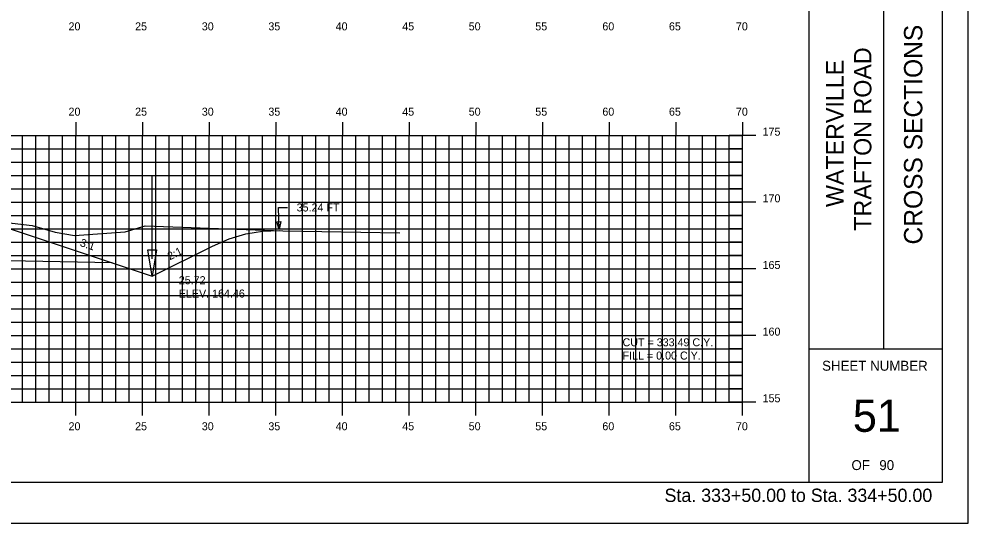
# Model space of a CAD drawing. Extents: x 1141868 to 1142038, y 608981 to 609091.
# Drawn here: x 1141966.5 to 1142037.7, y 608981.3 to 609019.1 of the extents above; entities that cross this region are included whole.
import ezdxf

# ---------------------------------------------------------------- set-up
doc = ezdxf.new("R2010")
doc.units = 0
for name, color, linetype in [('ANNOTATION', 7, 'Continuous'), ('BORDER', 7, 'Continuous'), ('D_Drainage_Ditch_Line', 7, 'Continuous'), ('D_Roadway_SlopeLines', 7, 'Continuous'), ('D_Roadway_SubGrade', 7, 'Continuous'), ('D_Text_Standard', 7, 'Continuous'), ('H_V ANNOTATION', 7, 'Continuous'), ('HIGHWAY_TITLE', 7, 'Continuous'), ('MAJOR', 7, 'Continuous'), ('MINOR', 7, 'Continuous'), ('PLOT BOUNDARY', 7, 'Continuous'), ('S_Roadway_Centerline', 7, 'Continuous')]:
    doc.layers.add(name, color=color, linetype=linetype)

msp = doc.modelspace()

# ---------------------------------------------------------------- linework, layer by layer
msp.add_lwpolyline([(1141914.544, 609003.78), (1141914.544, 609003.78), (1141915.794, 609003.711), (1141917.044, 609003.482), (1141918.294, 609003.095), (1141919.544, 609002.55), (1141925.059, 608999.792), (1141928.059, 609000.792), (1141935.783, 609003.367), (1141935.784, 609003.367), (1141939.784, 609003.527), (1141950.784, 609003.747), (1141961.784, 609003.527), (1141965.784, 609003.367), (1141973.507, 609000.792), (1141976.507, 608999.792), (1141981.022, 609002.05), (1141982.272, 609002.591), (1141983.522, 609002.965), (1141984.772, 609003.172), (1141986.022, 609003.211)])
at = {"layer": 'BORDER'}
for p, q in [((1142025.784, 608984.335), (1142025.784, 609089.335)), ((1142031.375, 608994.338), (1142031.375, 609029.338)), ((1142025.784, 608994.338), (1142035.784, 608994.338))]:
    msp.add_line(p, q, dxfattribs=at)
msp.add_lwpolyline([(1141875.784, 608984.335), (1142035.784, 608984.335), (1142035.784, 609089.335), (1141875.784, 609089.335)], close=True, dxfattribs=at)
at = {"layer": 'D_Drainage_Ditch_Line'}
msp.add_line((1141976.507, 609001.104), (1141976.508, 609007.348), dxfattribs=at)
msp.add_lwpolyline([(1141976.179, 609001.761), (1141976.835, 609001.761), (1141976.507, 608999.792)], close=True, dxfattribs=at)
at = {"layer": 'D_Roadway_SlopeLines'}
for points in [[(1141976.507, 608999.792), (1141981.022, 609002.05), (1141982.272, 609002.591), (1141983.522, 609002.965), (1141984.772, 609003.172), (1141986.022, 609003.211)], [(1141973.507, 609000.792), (1141976.507, 608999.792)]]:
    msp.add_lwpolyline(points, dxfattribs=at)
at = {"layer": 'D_Roadway_SubGrade'}
msp.add_lwpolyline([(1141961.784, 609003.11), (1141961.784, 609003.277), (1141965.784, 609003.117), (1141965.784, 609003.367), (1141965.784, 609003.367), (1141973.507, 609000.792), (1141961.784, 609001.027)], close=True, dxfattribs=at)
at = {"layer": 'D_Text_Standard'}
msp.add_lwpolyline([(1141986.022, 609003.3), (1141985.986, 609004.95), (1141986.666, 609004.95)], dxfattribs=at)
msp.add_lwpolyline([(1141986.022, 609003.3), (1141985.864, 609003.878), (1141986.155, 609003.885)], close=True, dxfattribs=at)
at = {"layer": 'MAJOR'}
for p, q in [((1141970.784, 609011.337), (1141970.784, 609010.335)), ((1141975.784, 609011.337), (1141975.784, 609010.335)), ((1141980.784, 609011.337), (1141980.784, 609010.335)), ((1141985.784, 609011.337), (1141985.784, 609010.335)), ((1141990.784, 609011.337), (1141990.784, 609010.335)), ((1141995.784, 609011.337), (1141995.784, 609010.335)), ((1142000.784, 609011.337), (1142000.784, 609010.335)), ((1142005.784, 609011.337), (1142005.784, 609010.335)), ((1142010.784, 609011.337), (1142010.784, 609010.335)), ((1142015.784, 609011.337), (1142015.784, 609010.335)), ((1142020.784, 609011.337), (1142020.784, 609010.335)), ((1141880.784, 609010.335), (1142020.784, 609010.335)), ((1141880.784, 609010.335), (1142020.784, 609010.335)), ((1141970.784, 608990.335), (1141970.784, 609010.335)), ((1141975.784, 608990.335), (1141975.784, 609010.335)), ((1141980.784, 608990.335), (1141980.784, 609010.335)), ((1141985.784, 608990.335), (1141985.784, 609010.335)), ((1141990.784, 608990.335), (1141990.784, 609010.335)), ((1141995.784, 608990.335), (1141995.784, 609010.335)), ((1142000.784, 608990.335), (1142000.784, 609010.335)), ((1142005.784, 608990.335), (1142005.784, 609010.335)), ((1142010.784, 608990.335), (1142010.784, 609010.335)), ((1142015.784, 608990.335), (1142015.784, 609010.335)), ((1142021.786, 609010.335), (1142019.782, 609010.335)), ((1142020.784, 608990.335), (1142020.784, 609010.335)), ((1142020.784, 608990.335), (1142020.784, 609010.335)), ((1141880.784, 609005.335), (1142020.784, 609005.335)), ((1142021.786, 609005.335), (1142019.782, 609005.335)), ((1141880.784, 609000.335), (1142020.784, 609000.335)), ((1142021.786, 609000.335), (1142019.782, 609000.335)), ((1141880.784, 608995.335), (1142020.784, 608995.335)), ((1142021.786, 608995.335), (1142019.782, 608995.335)), ((1141880.784, 608990.335), (1142020.784, 608990.335)), ((1141880.784, 608990.335), (1142020.784, 608990.335)), ((1141970.784, 608989.333), (1141970.784, 608990.335)), ((1141975.784, 608989.333), (1141975.784, 608990.335)), ((1141980.784, 608989.333), (1141980.784, 608990.335)), ((1141985.784, 608989.333), (1141985.784, 608990.335)), ((1141990.784, 608989.333), (1141990.784, 608990.335)), ((1141995.784, 608989.333), (1141995.784, 608990.335)), ((1142000.784, 608989.333), (1142000.784, 608990.335)), ((1142005.784, 608989.333), (1142005.784, 608990.335)), ((1142010.784, 608989.333), (1142010.784, 608990.335)), ((1142015.784, 608989.333), (1142015.784, 608990.335)), ((1142021.786, 608990.335), (1142019.782, 608990.335)), ((1142020.784, 608989.333), (1142020.784, 608990.335))]:
    msp.add_line(p, q, dxfattribs=at)
at = {"layer": 'MINOR'}
for p, q in [((1141966.784, 608990.335), (1141966.784, 609010.335)), ((1141967.784, 608990.335), (1141967.784, 609010.335)), ((1141968.784, 608990.335), (1141968.784, 609010.335)), ((1141969.784, 608990.335), (1141969.784, 609010.335)), ((1141971.784, 608990.335), (1141971.784, 609010.335)), ((1141972.784, 608990.335), (1141972.784, 609010.335)), ((1141973.784, 608990.335), (1141973.784, 609010.335)), ((1141974.784, 608990.335), (1141974.784, 609010.335)), ((1141976.784, 608990.335), (1141976.784, 609010.335)), ((1141977.784, 608990.335), (1141977.784, 609010.335)), ((1141978.784, 608990.335), (1141978.784, 609010.335)), ((1141979.784, 608990.335), (1141979.784, 609010.335)), ((1141981.784, 608990.335), (1141981.784, 609010.335)), ((1141982.784, 608990.335), (1141982.784, 609010.335)), ((1141983.784, 608990.335), (1141983.784, 609010.335)), ((1141984.784, 608990.335), (1141984.784, 609010.335)), ((1141986.784, 608990.335), (1141986.784, 609010.335)), ((1141987.784, 608990.335), (1141987.784, 609010.335)), ((1141988.784, 608990.335), (1141988.784, 609010.335)), ((1141989.784, 608990.335), (1141989.784, 609010.335)), ((1141991.784, 608990.335), (1141991.784, 609010.335)), ((1141992.784, 608990.335), (1141992.784, 609010.335)), ((1141993.784, 608990.335), (1141993.784, 609010.335)), ((1141994.784, 608990.335), (1141994.784, 609010.335)), ((1141996.784, 608990.335), (1141996.784, 609010.335)), ((1141997.784, 608990.335), (1141997.784, 609010.335)), ((1141998.784, 608990.335), (1141998.784, 609010.335)), ((1141999.784, 608990.335), (1141999.784, 609010.335)), ((1142001.784, 608990.335), (1142001.784, 609010.335)), ((1142002.784, 608990.335), (1142002.784, 609010.335)), ((1142003.784, 608990.335), (1142003.784, 609010.335)), ((1142004.784, 608990.335), (1142004.784, 609010.335)), ((1142006.784, 608990.335), (1142006.784, 609010.335)), ((1142007.784, 608990.335), (1142007.784, 609010.335)), ((1142008.784, 608990.335), (1142008.784, 609010.335)), ((1142009.784, 608990.335), (1142009.784, 609010.335)), ((1142011.784, 608990.335), (1142011.784, 609010.335)), ((1142012.784, 608990.335), (1142012.784, 609010.335)), ((1142013.784, 608990.335), (1142013.784, 609010.335)), ((1142014.784, 608990.335), (1142014.784, 609010.335)), ((1142016.784, 608990.335), (1142016.784, 609010.335)), ((1142017.784, 608990.335), (1142017.784, 609010.335)), ((1142018.784, 608990.335), (1142018.784, 609010.335)), ((1142019.784, 608990.335), (1142019.784, 609010.335)), ((1141880.784, 609009.335), (1142020.784, 609009.335)), ((1142020.784, 609009.335), (1142019.782, 609009.335)), ((1141880.784, 609008.335), (1142020.784, 609008.335)), ((1142020.784, 609008.335), (1142019.782, 609008.335)), ((1141880.784, 609007.335), (1142020.784, 609007.335)), ((1142020.784, 609007.335), (1142019.782, 609007.335)), ((1141880.784, 609006.335), (1142020.784, 609006.335)), ((1142020.784, 609006.335), (1142019.782, 609006.335)), ((1141880.784, 609004.335), (1142020.784, 609004.335)), ((1142020.784, 609004.335), (1142019.782, 609004.335)), ((1141880.784, 609003.335), (1142020.784, 609003.335)), ((1142020.784, 609003.335), (1142019.782, 609003.335)), ((1141880.784, 609002.335), (1142020.784, 609002.335)), ((1142020.784, 609002.335), (1142019.782, 609002.335)), ((1141880.784, 609001.335), (1142020.784, 609001.335)), ((1142020.784, 609001.335), (1142019.782, 609001.335)), ((1141880.784, 608999.335), (1142020.784, 608999.335)), ((1142020.784, 608999.335), (1142019.782, 608999.335)), ((1141880.784, 608998.335), (1142020.784, 608998.335)), ((1142020.784, 608998.335), (1142019.782, 608998.335)), ((1141880.784, 608997.335), (1142020.784, 608997.335)), ((1142020.784, 608997.335), (1142019.782, 608997.335)), ((1141880.784, 608996.335), (1142020.784, 608996.335)), ((1142020.784, 608996.335), (1142019.782, 608996.335)), ((1141880.784, 608994.335), (1142020.784, 608994.335)), ((1142020.784, 608994.335), (1142019.782, 608994.335)), ((1141880.784, 608993.335), (1142020.784, 608993.335)), ((1142020.784, 608993.335), (1142019.782, 608993.335)), ((1141880.784, 608992.335), (1142020.784, 608992.335)), ((1142020.784, 608992.335), (1142019.782, 608992.335)), ((1141880.784, 608991.335), (1142020.784, 608991.335)), ((1142020.784, 608991.335), (1142019.782, 608991.335))]:
    msp.add_line(p, q, dxfattribs=at)
at = {"layer": 'PLOT BOUNDARY'}
msp.add_lwpolyline([(1141867.691, 608981.276), (1142037.691, 608981.276), (1142037.691, 609091.276), (1141867.691, 609091.276)], close=True, dxfattribs=at)
at = {"layer": 'S_Roadway_Centerline'}
msp.add_lwpolyline([(1141900.602, 609003.644), (1141901.394, 609003.749), (1141915.746, 609003.783), (1141928.977, 609003.95), (1141931.483, 609003.382), (1141934.466, 609002.656), (1141935.906, 609003.083), (1141937.139, 609003.558), (1141939.061, 609003.555), (1141941.092, 609003.71), (1141946.4, 609003.848), (1141952.444, 609004.051), (1141957.538, 609004.023), (1141963.377, 609003.905), (1141965.582, 609003.828), (1141967.5, 609003.599), (1141969.235, 609003.105), (1141970.695, 609002.835), (1141974.484, 609003.124), (1141975.978, 609003.567), (1141986.319, 609003.2), (1141995.084, 609003.033)], dxfattribs=at)

# ---------------------------------------------------------------- texts
at = {"layer": 'ANNOTATION'}
for s, rotation, p in [('-3:1', 341.56521, (1141970.795, 609002.15)), ('2:1', 26.56505, (1141977.837, 609000.975))]:
    msp.add_text(s, height=0.6, rotation=rotation, dxfattribs=at).set_placement(p)
at = {"layer": 'BORDER'}
msp.add_text('CROSS SECTIONS', height=1.37787, rotation=90, dxfattribs=at).set_placement((1142034.268, 609002.172))
for s, height, p in [('SHEET NUMBER', 0.74527, (1142026.749, 608992.701)), ('51', 2.4194, (1142029.055, 608988.118)), ('OF', 0.7453, (1142028.951, 608985.248)), ('90', 0.7453, (1142031.04, 608985.248))]:
    msp.add_text(s, height=height, dxfattribs=at).set_placement(p)
at = {"layer": 'D_Text_Standard'}
for s, p in [('35.24 FT', (1141987.346, 609004.65)), ('25.72', (1141978.507, 608999.192)), ('ELEV. 164.46', (1141978.507, 608998.19)), ('CUT = 333.49 C.Y.', (1142011.784, 608994.535)), ('FILL = 0.00 C.Y.', (1142011.784, 608993.539))]:
    msp.add_text(s, height=0.6, dxfattribs=at).set_placement(p)
at = {"layer": 'H_V ANNOTATION'}
for s, height, p in [('20', 0.6, (1141970.238, 609018.235)), ('25', 0.6, (1141975.23, 609018.235)), ('30', 0.6, (1141980.232, 609018.235)), ('35', 0.6, (1141985.224, 609018.235)), ('40', 0.6, (1141990.27, 609018.235)), ('45', 0.6, (1141995.262, 609018.235)), ('50', 0.6, (1142000.248, 609018.235)), ('55', 0.6, (1142005.24, 609018.235)), ('60', 0.6, (1142010.27, 609018.235)), ('65', 0.6, (1142015.262, 609018.235)), ('70', 0.6, (1142020.286, 609018.235)), ('20', 0.6, (1141970.238, 609011.835)), ('25', 0.6, (1141975.23, 609011.835)), ('30', 0.6, (1141980.232, 609011.835)), ('35', 0.6, (1141985.224, 609011.835)), ('40', 0.6, (1141990.27, 609011.835)), ('45', 0.6, (1141995.262, 609011.835)), ('50', 0.6, (1142000.248, 609011.835)), ('55', 0.6, (1142005.24, 609011.835)), ('60', 0.6, (1142010.27, 609011.835)), ('65', 0.6, (1142015.262, 609011.835)), ('70', 0.6, (1142020.286, 609011.835)), ('175', 0.6, (1142022.284, 609010.335)), ('170', 0.6, (1142022.284, 609005.335)), ('165', 0.6, (1142022.284, 609000.335)), ('160', 0.6, (1142022.284, 608995.335)), ('155', 0.6, (1142022.284, 608990.335)), ('20', 0.6, (1141970.238, 608988.235)), ('25', 0.6, (1141975.23, 608988.235)), ('30', 0.6, (1141980.232, 608988.235)), ('35', 0.6, (1141985.224, 608988.235)), ('40', 0.6, (1141990.27, 608988.235)), ('45', 0.6, (1141995.262, 608988.235)), ('50', 0.6, (1142000.248, 608988.235)), ('55', 0.6, (1142005.24, 608988.235)), ('60', 0.6, (1142010.27, 608988.235)), ('65', 0.6, (1142015.262, 608988.235)), ('70', 0.6, (1142020.286, 608988.235)), ('Sta. 333+50.00 to Sta. 334+50.00', 1.0002, (1142014.93, 608982.855))]:
    msp.add_text(s, height=height, dxfattribs=at).set_placement(p)
at = {"layer": 'HIGHWAY_TITLE'}
for s, height, p in [('TRAFTON ROAD', 1.30428, (1142030.443, 609003.201)), ('WATERVILLE', 1.3043, (1142028.356, 609004.98))]:
    msp.add_text(s, height=height, rotation=90, dxfattribs=at).set_placement(p)

doc.saveas('drawing.dxf')
